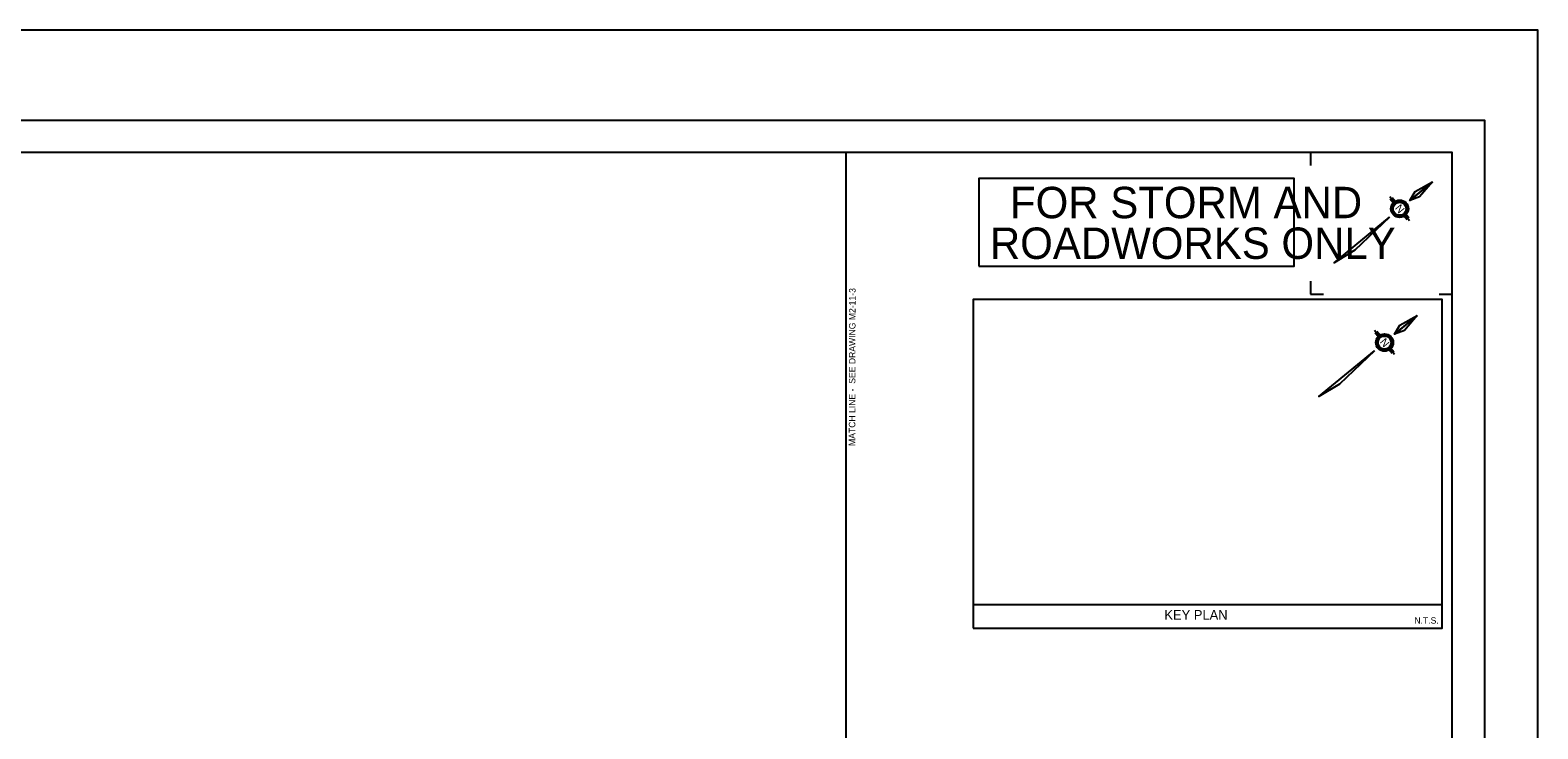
# Model space of a CAD drawing. Extents: x 595568 to 603709, y 4837996 to 4846716.
# Drawn here: x 603142.9 to 603377, y 4846537.1 to 4846645.6 of the extents above; entities that cross this region are included whole.
import ezdxf

# ---------------------------------------------------------------- set-up
doc = ezdxf.new("R2010")
doc.units = 0
for name, color, linetype in [('-PRINT FULLSIZE', 7, 'Continuous'), ('-PRINT HALFSIZE', 7, 'Continuous'), ('ENG_BORDER', 7, 'Continuous'), ('ENG_DIMENSIONS', 7, 'Continuous'), ('ENG_KEY', 7, 'Continuous'), ('ENG_LEGEND', 7, 'Continuous'), ('ENG_TITLEBLOCK', 7, 'Continuous'), ('ENG_TX_DIMENSIONS', 7, 'Continuous'), ('ENG_TX_LEGEND', 7, 'Continuous')]:
    doc.layers.add(name, color=color, linetype=linetype)

msp = doc.modelspace()

# ---------------------------------------------------------------- linework, layer by layer
at = {"layer": '-PRINT FULLSIZE'}
msp.add_lwpolyline([(602930, 4846340.65), (603377.03, 4846340.65), (603377.03, 4846645.65), (602930, 4846645.65)], close=True, dxfattribs=at)
at = {"layer": '-PRINT HALFSIZE'}
msp.add_lwpolyline([(602959.8, 4846631.64), (603368.72, 4846631.64), (603368.72, 4846352.64), (602959.8, 4846352.64)], close=True, dxfattribs=at)
at = {"layer": 'ENG_BORDER'}
msp.add_lwpolyline([(602975.52, 4846357.64), (603363.72, 4846357.64), (603363.72, 4846626.64), (602975.52, 4846626.64)], close=True, dxfattribs=at)
at = {"layer": 'ENG_DIMENSIONS'}
msp.add_line((603269.61, 4846500.41), (603269.61, 4846626.64), dxfattribs=at)
at = {"layer": 'ENG_KEY'}
for p, q in [((603352.36, 4846598.15), (603351.67, 4846598.99)), ((603352.23, 4846598.03), (603351.77, 4846598.59)), ((603352.51, 4846598.26), (603352.04, 4846598.82)), ((603354.39, 4846595.41), (603353.93, 4846595.97)), ((603354.77, 4846595.24), (603354.08, 4846596.07)), ((603354.67, 4846595.64), (603354.21, 4846596.2)), ((603289.33, 4846556.44), (603362.15, 4846556.44))]:
    msp.add_line(p, q, dxfattribs=at)
for points in [[(603289.33, 4846552.76), (603362.15, 4846552.76), (603362.15, 4846603.82), (603289.33, 4846603.82)], [(603358.31, 4846601.32), (603356.3, 4846598.96), (603354.79, 4846598.41)], [(603358.31, 4846601.32), (603354.79, 4846598.41), (603355.62, 4846599.8)], [(603351.65, 4846595.81), (603346.25, 4846590.66), (603343.04, 4846588.71)]]:
    msp.add_lwpolyline(points, close=True, dxfattribs=at)
for radius in [1.35, 1.25, 1.01]:
    msp.add_circle((603353.22, 4846597.11), radius, dxfattribs=at)
at = {"layer": 'ENG_LEGEND'}
msp.add_lwpolyline([(603290.23, 4846608.96), (603339.17, 4846608.96), (603339.17, 4846622.62), (603290.23, 4846622.62)], close=True, dxfattribs=at)
at = {"layer": 'ENG_TITLEBLOCK'}
for p, q in [((603341.72, 4846626.64), (603341.72, 4846624.64)), ((603354.71, 4846618.93), (603354.02, 4846619.77)), ((603354.58, 4846618.81), (603354.11, 4846619.37)), ((603354.85, 4846619.04), (603354.39, 4846619.6)), ((603356.74, 4846616.19), (603356.28, 4846616.75)), ((603357.11, 4846616.02), (603356.43, 4846616.85)), ((603357.02, 4846616.42), (603356.56, 4846616.98)), ((603341.72, 4846606.64), (603341.72, 4846604.64)), ((603341.72, 4846604.64), (603343.72, 4846604.64)), ((603361.72, 4846604.64), (603363.72, 4846604.64))]:
    msp.add_line(p, q, dxfattribs=at)
for points in [[(603360.66, 4846622.1), (603358.65, 4846619.74), (603357.14, 4846619.19)], [(603360.66, 4846622.1), (603357.14, 4846619.19), (603357.97, 4846620.58)], [(603353.99, 4846616.59), (603348.6, 4846611.44), (603345.39, 4846609.49)]]:
    msp.add_lwpolyline(points, close=True, dxfattribs=at)
for radius in [1.35, 1.25, 1.01]:
    msp.add_circle((603355.57, 4846617.89), radius, dxfattribs=at)

# ---------------------------------------------------------------- texts
at = {"layer": 'ENG_KEY'}
msp.add_text('N', height=1.2, rotation=309.5559, dxfattribs=at).set_placement((603352.43, 4846597.17))
at = {"layer": 'ENG_TITLEBLOCK'}
msp.add_text('N', height=1.2, rotation=309.5559, dxfattribs=at).set_placement((603354.77, 4846617.96))
at = {"layer": 'ENG_TX_DIMENSIONS'}
msp.add_text('MATCH LINE -  SEE DRAWING M2-11-3', height=1, rotation=89.8783, dxfattribs=at).set_placement((603271.03, 4846581.05))
at = {"layer": 'ENG_TX_LEGEND'}
for s, height, p in [('FOR STORM AND', 4.875, (603295.06, 4846616.43)), ('ROADWORKS ONLY', 4.875, (603291.94, 4846610.11)), ('KEY PLAN', 1.5, (603319.04, 4846554.06)), ('N.T.S.', 1, (603357.85, 4846553.45))]:
    msp.add_text(s, height=height, rotation=360, dxfattribs=at).set_placement(p)

doc.saveas('drawing.dxf')
